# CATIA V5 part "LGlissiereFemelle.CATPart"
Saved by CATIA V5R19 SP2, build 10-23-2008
Part number: GlissièreFemelle
Publications: "Centre", "Axe", "Plan", "Facteur d'échelle"
Bounding box of the stored display mesh (mm): x -12.5 to 12.5, y -12.5 to 12.5, z -25 to 25
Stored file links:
  E:\Mes documents\03_Ressources pédagogiques\01_Catia\Buggy Dassault\SchemaCinematiqueFinal\LGlissiereFemelle.CATPart
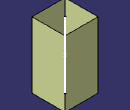
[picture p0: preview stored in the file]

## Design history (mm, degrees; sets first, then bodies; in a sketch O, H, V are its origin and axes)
Parameters
  `Facteur d'échelle` = 5
Body1 "GlissièreFemelle" (main body)
  Point1 "Centre": (0, 0, 0)
  Line1 "Axe": type PtPt, FirstPoint {point type Coord, X 0, Y 0, Z -25 {= -5mm*`Facteur d'échelle`}}, SecondPoint {point type Coord, X 0, Y 0, Z 25 {= 5mm*`Facteur d'échelle`}}, Support zx-plane
  Sketch1 on xy-plane, origin (0, 0, 0), H (1, 0, 0), V (0, 1, 0)
    line L1 (12.5, 12.5) -> (12.5, -12.5)
    line L2 (12.5, -12.5) -> (-12.5, -12.5)
    line L3 (-12.5, -12.5) -> (-12.5, 12.5)
    line L4 (-12.5, 12.5) -> (12.5, 12.5)
    distance L2 L4 = 25 {= 5mm*`Facteur d'échelle`}
    distance L1 L3 = 25 {= 5mm*`Facteur d'échelle`}
    vertical: L1 V, L3 V
    horizontal: L2 H, L4 H
    equidistance: L1 L3 O, L2 L4 O
  Extrude1 "Extrusion.1": Element1 Sketch1, Lim1 25 {= 5mm*`Facteur d'échelle`}, Lim2 25 {= 5mm*`Facteur d'échelle`}, Direction xy-plane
